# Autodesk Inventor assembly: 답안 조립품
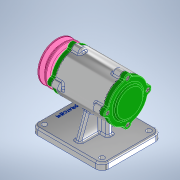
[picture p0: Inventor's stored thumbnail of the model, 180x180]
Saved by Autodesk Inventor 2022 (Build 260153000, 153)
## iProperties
Created: 2023-05
Part Number: 답안 조립품
Document SubType Name: Assembly
Designer: Admin
Author: Admin
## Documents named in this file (12)
- C:\Users\Admin\Desktop\730508V1002\답안 조립품.iam
- C:\Users\Admin\Desktop\730508V1002\본체.ipt
- C:\Users\Admin\Desktop\730508V1002\개스킷.ipt
- C:\Users\Admin\Desktop\730508V1002\앞커버.ipt
- C:\Users\Admin\Desktop\730508V1002\뒤커버.ipt
- C:\Users\Admin\Desktop\730508V1002\베어링 6204.ipt
- C:\Users\Admin\Desktop\730508V1002\오일 실.ipt
- C:\Users\Admin\Desktop\730508V1002\축.ipt
- C:\Users\Admin\Desktop\730508V1002\볼트 M4 x 12.ipt
- C:\Users\Admin\Desktop\730508V1002\Ű 4 x 4.ipt
- C:\Users\Admin\Desktop\730508V1002\V-벨트풀리.ipt
- C:\Users\Admin\Desktop\730508V1002\너트 M12 x 1.25.ipt
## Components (8 placed, 6 different names)
1. 개스킷:1
2. 개스킷:2
3. KS B 2023 6204 - 20 x 47 x 14:1
4. KS B 2023 6204 - 20 x 47 x 14:2
5. KS B 2804 D D - 20 32 8:1
6. KS B 1311 (I) 4 x 4 x 12:1
7. V-벨트풀리:1
8. KS B 1012 클래스 1 일반 - 미터 M12x1.25:1
